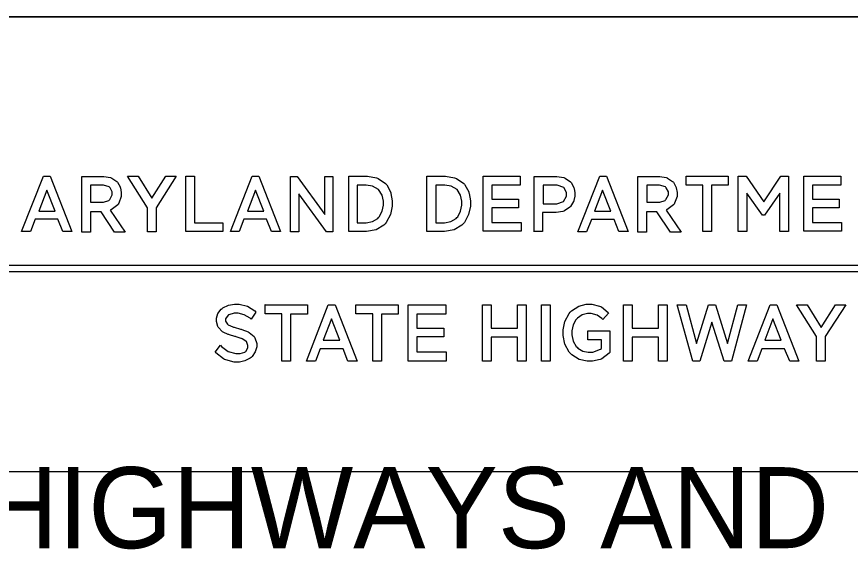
# Model space of a CAD drawing. Extents: x -111.7 to -103.2, y -200 to -189.
# Drawn here: x -106.489 to -105.536, y -198.828 to -198.218 of the extents above; entities that cross this region are included whole.
import ezdxf

# ---------------------------------------------------------------- set-up
doc = ezdxf.new("R2010")
doc.units = 0
for name, color, linetype in [('BORD-LINE', 7, 'Continuous'), ('MSHA-LOGO', 7, 'Continuous'), ('TTLB-TEXT', 7, 'Continuous'), ('USER-LINE', 7, 'Continuous')]:
    doc.layers.add(name, color=color, linetype=linetype)

msp = doc.modelspace()

# ---------------------------------------------------------------- linework, layer by layer
at = {"layer": 'BORD-LINE'}
msp.add_line((-103.54884, -198.21844), (-108.02174, -198.21844), dxfattribs=at)
at = {"layer": 'MSHA-LOGO'}
for points in [[(-106.45811, -198.40084), (-106.45058, -198.40084), (-106.42571, -198.46432), (-106.43617, -198.46432), (-106.44175, -198.45018), (-106.46759, -198.45018), (-106.47316, -198.46432), (-106.4833, -198.46432)], [(-106.41426, -198.46466), (-106.41426, -198.40116), (-106.392, -198.40116), (-106.38922, -198.40116), (-106.38168, -198.40255), (-106.38087, -198.40281), (-106.38013, -198.40305), (-106.37441, -198.40692), (-106.374, -198.40742), (-106.37359, -198.4079), (-106.37066, -198.41309), (-106.3704, -198.41367), (-106.37025, -198.41424), (-106.36941, -198.41948), (-106.36941, -198.42123), (-106.36941, -198.42411), (-106.37212, -198.43192), (-106.37268, -198.43274), (-106.37326, -198.43356), (-106.38088, -198.43932), (-106.38185, -198.43965), (-106.36484, -198.46499), (-106.37695, -198.46499), (-106.39232, -198.44163), (-106.40444, -198.44163), (-106.40444, -198.46499), (-106.41426, -198.46499)], [(-106.32949, -198.43702), (-106.32949, -198.46466), (-106.33931, -198.46466), (-106.33931, -198.43702), (-106.36222, -198.40084), (-106.35012, -198.40084), (-106.3344, -198.42616), (-106.31836, -198.40084), (-106.30659, -198.40084)], [(-106.29546, -198.40084), (-106.28564, -198.40084), (-106.28564, -198.45412), (-106.25324, -198.45412), (-106.25324, -198.46432), (-106.29546, -198.46432)], [(-106.21954, -198.40084), (-106.21201, -198.40084), (-106.18714, -198.46432), (-106.1976, -198.46432), (-106.20318, -198.45018), (-106.22904, -198.45018), (-106.23459, -198.46432), (-106.24441, -198.46432)], [(-106.13478, -198.46466), (-106.16619, -198.42123), (-106.16619, -198.46466), (-106.17568, -198.46466), (-106.17568, -198.40116), (-106.16815, -198.40116), (-106.13674, -198.44458), (-106.13674, -198.40116), (-106.12724, -198.40116), (-106.12724, -198.46466)], [(-106.10925, -198.40084), (-106.09159, -198.40084), (-106.08782, -198.40084), (-106.0776, -198.40272), (-106.07652, -198.40313), (-106.07546, -198.40354), (-106.06705, -198.4093), (-106.06638, -198.41004), (-106.06582, -198.41078), (-106.0614, -198.419), (-106.06115, -198.41991), (-106.06091, -198.42082), (-106.05951, -198.42902), (-106.05951, -198.43176), (-106.05951, -198.43502), (-106.06152, -198.44482), (-106.06631, -198.45387), (-106.06769, -198.45544), (-106.06909, -198.45692), (-106.07804, -198.46209), (-106.08893, -198.46432), (-106.09256, -198.46432), (-106.10925, -198.46432)], [(-106.01992, -198.40084), (-106.00224, -198.40084), (-105.99849, -198.40084), (-105.98826, -198.40272), (-105.98719, -198.40313), (-105.98614, -198.40354), (-105.97772, -198.4093), (-105.97705, -198.41004), (-105.97649, -198.41078), (-105.97206, -198.419), (-105.9718, -198.41991), (-105.97156, -198.42082), (-105.97016, -198.42902), (-105.97016, -198.43176), (-105.97016, -198.43502), (-105.97217, -198.44482), (-105.97696, -198.45387), (-105.97834, -198.45544), (-105.97974, -198.45692), (-105.98871, -198.46209), (-105.9996, -198.46432), (-106.00323, -198.46432), (-106.01992, -198.46432)], [(-105.95543, -198.40084), (-105.91324, -198.40084), (-105.91324, -198.41103), (-105.94562, -198.41103), (-105.94562, -198.42715), (-105.9152, -198.42715), (-105.9152, -198.43702), (-105.94562, -198.43702), (-105.94562, -198.4538), (-105.91225, -198.4538), (-105.91225, -198.46399), (-105.95543, -198.46399)], [(-105.8972, -198.46466), (-105.8972, -198.40116), (-105.87429, -198.40116), (-105.87136, -198.40116), (-105.86333, -198.40255), (-105.86252, -198.40281), (-105.8617, -198.40313), (-105.85571, -198.40725), (-105.8553, -198.40774), (-105.85489, -198.40822), (-105.85188, -198.41374), (-105.8517, -198.41432), (-105.85155, -198.41489), (-105.85072, -198.42013), (-105.85072, -198.4219), (-105.85072, -198.42378), (-105.85179, -198.42887), (-105.85203, -198.42945), (-105.85229, -198.43002), (-105.85556, -198.43553), (-105.85597, -198.43603), (-105.85637, -198.43651), (-105.86267, -198.44062), (-105.86348, -198.44096), (-105.8643, -198.44129), (-105.87204, -198.44261), (-105.87461, -198.44261), (-105.8877, -198.44261), (-105.8877, -198.46432), (-105.8972, -198.46432)], [(-105.82225, -198.40084), (-105.81472, -198.40084), (-105.78985, -198.46432), (-105.80034, -198.46432), (-105.80589, -198.45051), (-105.83175, -198.45051), (-105.8373, -198.46466), (-105.84744, -198.46466)], [(-105.77872, -198.46466), (-105.77872, -198.40116), (-105.75648, -198.40116), (-105.7537, -198.40116), (-105.74617, -198.40255), (-105.74535, -198.40281), (-105.74462, -198.40305), (-105.73889, -198.40692), (-105.73848, -198.40742), (-105.73807, -198.4079), (-105.73514, -198.41309), (-105.73489, -198.41367), (-105.73473, -198.41424), (-105.73389, -198.41948), (-105.73389, -198.42123), (-105.73389, -198.42411), (-105.73661, -198.43192), (-105.73717, -198.43274), (-105.73775, -198.43356), (-105.74537, -198.43932), (-105.74634, -198.43965), (-105.72931, -198.46499), (-105.74143, -198.46499), (-105.7568, -198.44163), (-105.7689, -198.44163), (-105.7689, -198.46499), (-105.77872, -198.46499)], [(-105.72343, -198.40084), (-105.67531, -198.40084), (-105.67531, -198.41103), (-105.69462, -198.41103), (-105.69462, -198.46432), (-105.70444, -198.46432), (-105.70444, -198.41103), (-105.72343, -198.41103)], [(-105.66386, -198.40084), (-105.65503, -198.40084), (-105.63473, -198.43044), (-105.61509, -198.40084), (-105.60659, -198.40084), (-105.60659, -198.46432), (-105.61641, -198.46432), (-105.61641, -198.42025), (-105.63376, -198.44557), (-105.63637, -198.44557), (-105.65404, -198.42025), (-105.65404, -198.46432), (-105.66386, -198.46432)], [(-105.58891, -198.40084), (-105.54672, -198.40084), (-105.54672, -198.41103), (-105.5791, -198.41103), (-105.5791, -198.42715), (-105.54867, -198.42715), (-105.54867, -198.43702), (-105.5791, -198.43702), (-105.5791, -198.4538), (-105.54572, -198.4538), (-105.54572, -198.46399), (-105.58891, -198.46399)], [(-106.40444, -198.41136), (-106.40444, -198.43077), (-106.39167, -198.43077), (-106.38947, -198.43077), (-106.38342, -198.42854), (-106.38284, -198.42813), (-106.38235, -198.42772), (-106.37957, -198.42236), (-106.37957, -198.42058), (-106.37957, -198.41885), (-106.38202, -198.41409), (-106.3825, -198.41367), (-106.383, -198.41326), (-106.38975, -198.41136), (-106.392, -198.41136)], [(-106.09943, -198.41136), (-106.09943, -198.45412), (-106.09191, -198.45412), (-106.08946, -198.45412), (-106.0821, -198.45264), (-106.07613, -198.44919), (-106.07523, -198.44821), (-106.07432, -198.44722), (-106.07108, -198.44109), (-106.06965, -198.4341), (-106.06965, -198.43176), (-106.06965, -198.42948), (-106.07102, -198.42268), (-106.07511, -198.41621), (-106.08196, -198.41232), (-106.08919, -198.41103), (-106.09159, -198.41103), (-106.09943, -198.41103)], [(-106.00978, -198.41136), (-106.00978, -198.45412), (-106.00224, -198.45412), (-105.99979, -198.45412), (-105.99242, -198.45264), (-105.98646, -198.44919), (-105.98556, -198.44821), (-105.98467, -198.44722), (-105.98143, -198.44109), (-105.97998, -198.4341), (-105.97998, -198.43176), (-105.97998, -198.42948), (-105.98135, -198.42268), (-105.98543, -198.41621), (-105.99229, -198.41232), (-105.99951, -198.41103), (-106.00192, -198.41103), (-106.00978, -198.41103)], [(-105.88706, -198.41103), (-105.88706, -198.43242), (-105.87397, -198.43242), (-105.87139, -198.43242), (-105.86365, -198.42969), (-105.86021, -198.42358), (-105.86021, -198.42155), (-105.86021, -198.41958), (-105.86345, -198.41369), (-105.87085, -198.41103), (-105.8733, -198.41103)], [(-105.76858, -198.41136), (-105.76858, -198.43077), (-105.75581, -198.43077), (-105.75362, -198.43077), (-105.74757, -198.42854), (-105.74699, -198.42813), (-105.74651, -198.42772), (-105.74371, -198.42236), (-105.74371, -198.42058), (-105.74371, -198.41885), (-105.74618, -198.41409), (-105.74666, -198.41367), (-105.74715, -198.41326), (-105.75391, -198.41136), (-105.75616, -198.41136)], [(-106.46367, -198.44096), (-106.44502, -198.44096), (-106.4545, -198.41696)], [(-106.2251, -198.44096), (-106.20645, -198.44096), (-106.21594, -198.41696)], [(-105.82815, -198.44096), (-105.80948, -198.44096), (-105.81898, -198.41696)], [(-106.55263, -198.50259), (-104.43595, -198.50259), (-104.43595, -198.51047), (-106.55263, -198.51047)], [(-106.22653, -198.58988), (-106.22687, -198.58955), (-106.23109, -198.5869), (-106.23164, -198.58667), (-106.23221, -198.5865), (-106.23805, -198.58456), (-106.23868, -198.58441), (-106.23933, -198.58424), (-106.2457, -198.5824), (-106.24634, -198.58217), (-106.24699, -198.58192), (-106.25283, -198.57928), (-106.25338, -198.57896), (-106.25394, -198.57862), (-106.25817, -198.57404), (-106.25848, -198.57349), (-106.25882, -198.57292), (-106.2604, -198.56708), (-106.2604, -198.56514), (-106.2604, -198.56339), (-106.25877, -198.55812), (-106.25506, -198.55317), (-106.25401, -198.5523), (-106.25298, -198.55141), (-106.24684, -198.5484), (-106.24, -198.54717), (-106.23772, -198.54717), (-106.23454, -198.54717), (-106.22499, -198.54952), (-106.21672, -198.55494), (-106.21535, -198.55648), (-106.22078, -198.56451), (-106.22197, -198.56337), (-106.2287, -198.55944), (-106.2357, -198.55777), (-106.23803, -198.55777), (-106.2402, -198.55777), (-106.24612, -198.55936), (-106.24667, -198.55969), (-106.24723, -198.56001), (-106.25018, -198.56409), (-106.25018, -198.56546), (-106.25018, -198.56675), (-106.24802, -198.57021), (-106.24762, -198.57061), (-106.24722, -198.57093), (-106.24164, -198.57332), (-106.24091, -198.57349), (-106.2402, -198.57364), (-106.23309, -198.57581), (-106.23229, -198.57607), (-106.23149, -198.5763), (-106.2243, -198.57903), (-106.22365, -198.57928), (-106.22302, -198.57959), (-106.21743, -198.58441), (-106.21695, -198.58506), (-106.21655, -198.5857), (-106.21439, -198.59219), (-106.21439, -198.59436), (-106.21439, -198.59627), (-106.21603, -198.60199), (-106.21974, -198.60729), (-106.22078, -198.60818), (-106.22182, -198.60905), (-106.2279, -198.61222), (-106.2343, -198.61363), (-106.23643, -198.61363), (-106.24011, -198.61363), (-106.24993, -198.61097), (-106.25113, -198.61042), (-106.25233, -198.60985), (-106.26136, -198.60287), (-106.262, -198.60207), (-106.25592, -198.59436), (-106.25466, -198.59588), (-106.24704, -198.6013), (-106.23838, -198.60368), (-106.23549, -198.60368), (-106.23349, -198.60368), (-106.22798, -198.60207), (-106.2275, -198.60175), (-106.22702, -198.60142), (-106.22462, -198.59732), (-106.22462, -198.59597), (-106.22462, -198.59445), (-106.22622, -198.5902)], [(-106.20513, -198.54814), (-106.15656, -198.54814), (-106.15656, -198.55872), (-106.17573, -198.55872), (-106.17573, -198.61236), (-106.18563, -198.61236), (-106.18563, -198.5584), (-106.2048, -198.5584), (-106.2048, -198.54814)], [(-106.1326, -198.54814), (-106.12492, -198.54814), (-106.0997, -198.61236), (-106.11023, -198.61236), (-106.11567, -198.59823), (-106.14186, -198.59823), (-106.14729, -198.61236), (-106.15752, -198.61236)], [(-106.10129, -198.54814), (-106.05272, -198.54814), (-106.05272, -198.55872), (-106.07189, -198.55872), (-106.07189, -198.61236), (-106.08179, -198.61236), (-106.08179, -198.5584), (-106.10096, -198.5584), (-106.10096, -198.54814)], [(-106.04122, -198.54814), (-105.9984, -198.54814), (-105.9984, -198.55872), (-106.03132, -198.55872), (-106.03132, -198.57478), (-106.00065, -198.57478), (-106.00065, -198.58473), (-106.03132, -198.58473), (-106.03132, -198.60175), (-105.99777, -198.60175), (-105.99777, -198.61236), (-106.04122, -198.61236)], [(-105.91629, -198.58506), (-105.94633, -198.58506), (-105.94633, -198.61236), (-105.95623, -198.61236), (-105.95623, -198.54814), (-105.94633, -198.54814), (-105.94633, -198.57478), (-105.91629, -198.57478), (-105.91629, -198.54814), (-105.90639, -198.54814), (-105.90639, -198.61236), (-105.91629, -198.61236)], [(-105.88882, -198.54814), (-105.8789, -198.54814), (-105.8789, -198.61236), (-105.88882, -198.61236)], [(-105.83576, -198.57799), (-105.81085, -198.57799), (-105.81085, -198.60272), (-105.8115, -198.60353), (-105.81981, -198.6097), (-105.82076, -198.6101), (-105.82181, -198.61057), (-105.83061, -198.61268), (-105.83354, -198.61268), (-105.8366, -198.61268), (-105.84577, -198.61045), (-105.85416, -198.6052), (-105.85559, -198.60368), (-105.85704, -198.60214), (-105.86206, -198.59324), (-105.8642, -198.58324), (-105.8642, -198.57991), (-105.8642, -198.5767), (-105.86209, -198.56712), (-105.85727, -198.55809), (-105.8559, -198.55648), (-105.85447, -198.55488), (-105.84632, -198.54941), (-105.8377, -198.54717), (-105.83482, -198.54717), (-105.83147, -198.54717), (-105.82244, -198.54957), (-105.82139, -198.55006), (-105.82044, -198.55053), (-105.8127, -198.55697), (-105.81214, -198.55777), (-105.81884, -198.56483), (-105.81973, -198.56369), (-105.82531, -198.55976), (-105.83195, -198.55809), (-105.83417, -198.55809), (-105.83622, -198.55809), (-105.84232, -198.55956), (-105.84768, -198.56314), (-105.84855, -198.56419), (-105.84943, -198.56514), (-105.85259, -198.57111), (-105.85399, -198.57795), (-105.85399, -198.58025), (-105.85399, -198.58255), (-105.85256, -198.58951), (-105.8492, -198.59557), (-105.84823, -198.59662), (-105.84729, -198.59757), (-105.84174, -198.60093), (-105.8356, -198.60239), (-105.83354, -198.60239), (-105.83027, -198.60239), (-105.82132, -198.59863), (-105.82044, -198.59791), (-105.82044, -198.58794), (-105.83576, -198.58794)], [(-105.75526, -198.58506), (-105.7853, -198.58506), (-105.7853, -198.61236), (-105.7952, -198.61236), (-105.7952, -198.54814), (-105.7853, -198.54814), (-105.7853, -198.57478), (-105.75526, -198.57478), (-105.75526, -198.54814), (-105.74536, -198.54814), (-105.74536, -198.61236), (-105.75526, -198.61236)], [(-105.67155, -198.61236), (-105.67986, -198.61236), (-105.69392, -198.56772), (-105.70765, -198.61236), (-105.71595, -198.61236), (-105.73386, -198.54814), (-105.72362, -198.54814), (-105.71149, -198.59244), (-105.69806, -198.54814), (-105.69007, -198.54814), (-105.67634, -198.59244), (-105.66451, -198.54814), (-105.65461, -198.54814)], [(-105.62745, -198.54814), (-105.61978, -198.54814), (-105.59453, -198.61236), (-105.60509, -198.61236), (-105.61085, -198.59823), (-105.63704, -198.59823), (-105.64246, -198.61236), (-105.6527, -198.61236)], [(-105.56452, -198.58441), (-105.56452, -198.61236), (-105.57442, -198.61236), (-105.57442, -198.58441), (-105.59741, -198.54814), (-105.58495, -198.54814), (-105.56897, -198.57382), (-105.55268, -198.54814), (-105.54087, -198.54814)], [(-106.13835, -198.58859), (-106.1195, -198.58859), (-106.12908, -198.56419)], [(-105.63353, -198.58859), (-105.61467, -198.58859), (-105.62426, -198.56419)]]:
    msp.add_lwpolyline(points, close=True, dxfattribs=at)
at = {"layer": 'USER-LINE'}
msp.add_lwpolyline([(-104.29972, -198.73914), (-107.27085, -198.73914), (-107.27085, -198.21844), (-104.29972, -198.21844)], close=True, dxfattribs=at)

# ---------------------------------------------------------------- texts
at = {"layer": 'TTLB-TEXT'}
msp.add_text('STANDARDS FOR HIGHWAYS AND INCIDENTAL STRUCTURES', height=0.0926898, dxfattribs=at).set_placement((-107.62594, -198.82644))

doc.saveas('drawing.dxf')
